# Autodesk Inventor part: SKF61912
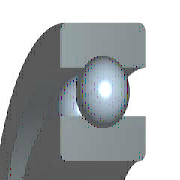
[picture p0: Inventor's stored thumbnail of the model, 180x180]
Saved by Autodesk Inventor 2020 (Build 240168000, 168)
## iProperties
Created: 2019-01
Part Number: SKF61912
Material: Acier, doux
Description: Roulements à bille à gorge profonde, rangée unique
Document SubType Name: Modeling
Standard: SKF
Designer: bruno
Language: fr-FR
Size Designation: SKF61912
Categories: <MemberInstance><Categories><Category DisplayName="Pièces d'arbre" InternalName="7f7aeb1f-a693-4053-b835-cee3144e0d98" Mnemonic="SHFT"><Category DisplayName="Ro
Density: 7.85 g/cm^3
Appearance: Semi-poli
IsCustomPart: 0
Author: bruno
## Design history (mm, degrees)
node "WorkPoint1"
node "WorkAxis1"
node "WorkPlane3"
node "WorkPlane4"
node "WorkPoint2"
pattern_circular "RéseauPolaire1" dims "d17" = 149 (= msp_pocet), angle "d19" = 360 deg
body "Solid1"
node "Esquisse1"
revolve "Révolution1" stored, may be unused: angle "d6" = 360 deg
revolve "Révolution2" stored, may be unused: angle "d10" = 360 deg
node "Esquisse4"
revolve "Révolution3" stored, may be unused: angle "d16" = 360 deg
fillet "Congé1" dims "d20" = 1 (= r)
sketch "Esquisse2"
  geometry: L1 (30, 13)-(42.5, 13); L2 (30, 0)-(30, 13); L3 (42.5, 0)-(30, 0); L4 (42.5, 13)-(42.5, 0); L5 (0, 0)-(0, 20); L6 (0, 0)-(0, 20); L7 (-7.2, 0)-(43.2, 0) reference
  constraints: 12 end point, 3 vertical, 2 horizontal, 1 collinear, 1 other
  dimensions: "d1" = 60 diameter of L1.start L5 (= Diam); "d3" = 85 diameter of L1.end L5 (= DD); "d5" = 13 distance of L2.start L1.start (= msp_mdtd2)
sketch "Esquisse3"
  geometry: L1 (38.5, 13)-(38.5, 9.5); L2 (34, 13)-(38.5, 13); L3 (34, 9.5)-(34, 13); L4 (34, 0)-(34, 3.5); L5 (38.5, 0)-(34, 0); L6 (38.5, 3.5)-(38.5, 0); L7 (42.5, 0)-(-42.5, 0) reference; L8 (42.5, 13)-(-42.5, 13) reference; L9 (0, -42.29)-(0, 61.29); L10 (0, 82.007)-(0, -63.007) reference; A1 r 3.75 centre (36.25, 6.5) between (38.5, 3.5) and (38.5, 9.5); A2 r 3.75 centre (36.25, 6.5) between (34, 9.5) and (34, 3.5)
  constraints: 14 end point, 4 collinear, 4 point on circle, 4 vertical, 2 centre point, 2 concentric, 2 horizontal, 2 point on line
  dimensions: "d9" = 7.5 diameter of A1 (= msp_mdtd6); "d21" = 34 distance between parallel lines of L9 L4 (= 0.5 x msp_d1); "d22" = 36.25 distance from line of L9 A1.centre (= 0.5 x msp_ds); "d23" = 38.5 distance between parallel lines of L9 L6 (= 0.5 x msp_dd1)
sketch "Esquisse5"
  geometry: L1 (36.25, 2.75)-(36.25, 10.25); L2 (38.5, 0)-(-38.5, 0) reference; L3 (36.25, 2.75)-(36.25, 10.25); A1 r 3.75 centre (36.25, 6.5) between (36.25, 2.75) and (36.25, 10.25); A2 r 3.75 centre (36.25, 6.5) between (38.5, 3.5) and (38.5, 9.5) reference
  constraints: 4 end point, 2 point on circle, 1 centre point, 1 concentric, 1 vertical
  dimensions: "d13" = 0 horizontal distance of A1.centre L1.start; "d15" = 7.5001 diameter of A1 (computed from msp_mdtd6)
other parameters: "Diam" = 60 [user parameter; used in 3 equation terms], "DD" = 85 [user parameter; used in 3 equation terms], "B" = 13 [user parameter; used in 1 equation term], "r" = 1 [user parameter; used in 1 equation term], "msp_ds" = 72.5 (= 0.5 x Diam + 0.5 x DD) [user parameter; used in 5 equation terms], "msp_d0" = 7.5 (= -0.3 x Diam + 0.3 x DD) [user parameter; used in 4 equation terms], "msp_d1" = 68 (= msp_ds - 0.6 x msp_d0) [user parameter; used in 1 equation term], "msp_dd1" = 77 (= msp_ds + 0.6 x msp_d0) [user parameter; used in 1 equation term], "msp_pom" = 108.75 (= 1.5 x msp_ds) [user parameter; used in 1 equation term], "msp_mdtd2" = 13 (= B) [user parameter; used in 3 equation terms], "msp_mdtd4" = 72.5 (= msp_ds) [user parameter], "msp_mdtd6" = 7.5 (= msp_d0) [user parameter; used in 2 equation terms], "msp_mdtd7" = 6.5 (= 0.5 x msp_mdtd2) [user parameter], "msp_pocet" = 149 (computed from msp_d0, msp_pom) [user parameter; used in 1 equation term], "d2" = 72 (derived), "d4" = 19 (derived), "d7" = 0, "d8" = 15.6 (derived), "d11" = -13 (computed from msp_mdtd2), "d12" = 0 (derived), "d14" = 15.6001 (derived), "d26" = 0, "d27" = 0, "d28" = 0, "d29" = 0, "d30" = 0
